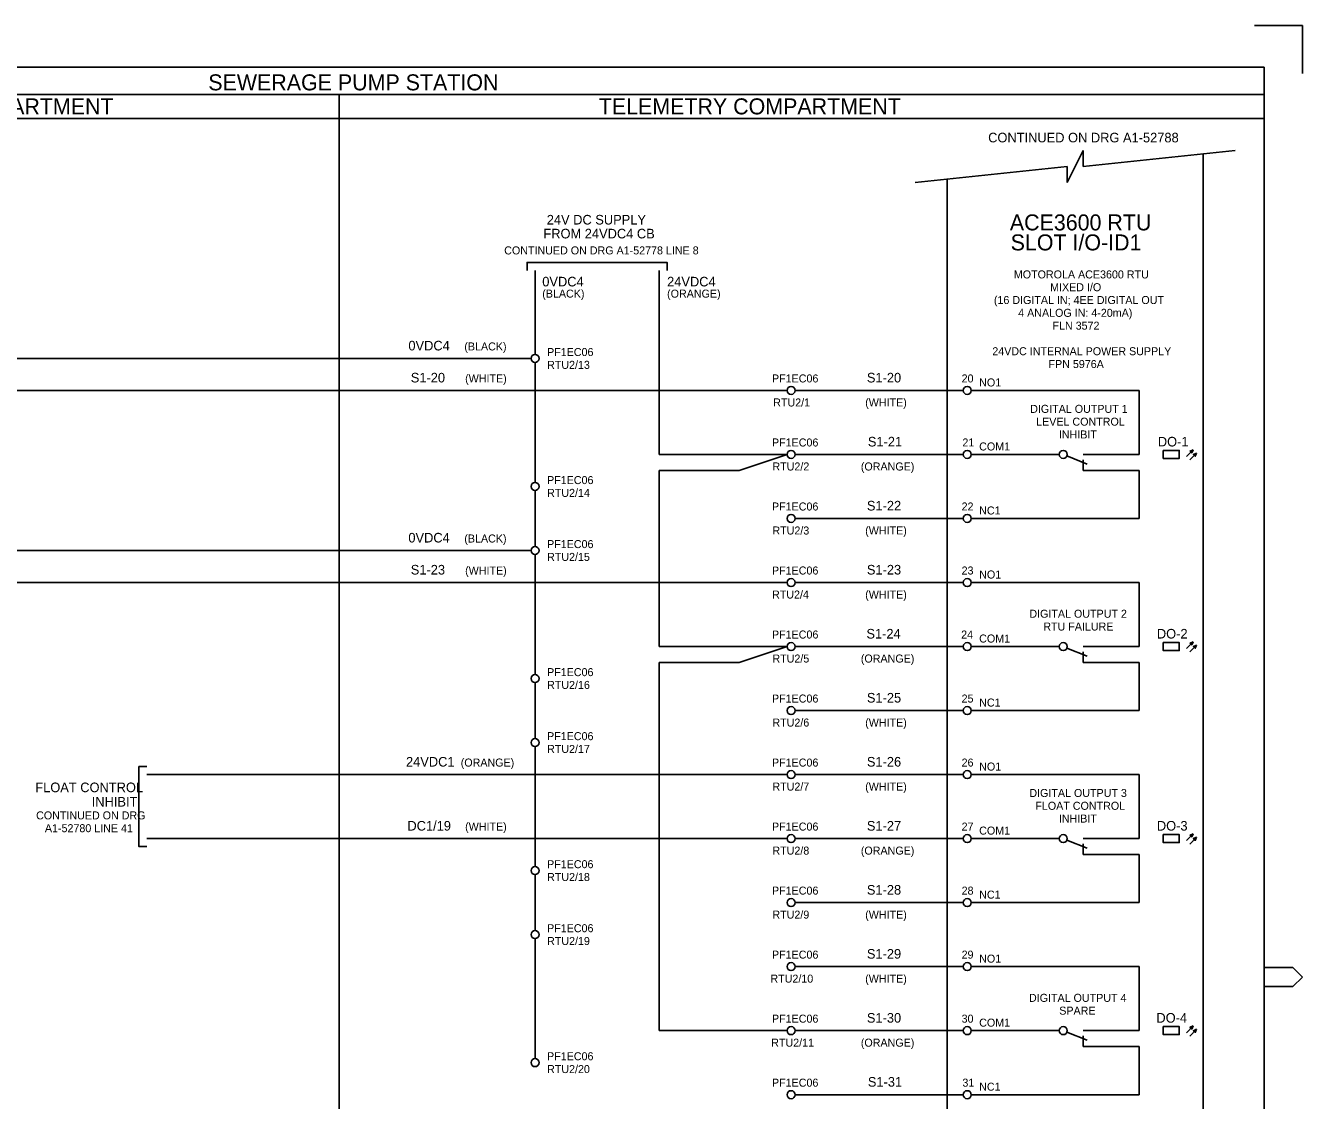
# Model space of a CAD drawing. Extents: x 0 to 841, y 0 to 594.
# Drawn here: x 442.1 to 841, y 258.2 to 594 of the extents above; entities that cross this region are included whole.
import ezdxf

# ---------------------------------------------------------------- set-up
doc = ezdxf.new("R2010")
doc.units = 0
for name, color, linetype in [('A1BORDER', 7, 'Continuous'), ('Level 1', 7, 'Continuous'), ('Level 10', 7, 'Continuous'), ('Level 2', 7, 'Continuous')]:
    doc.layers.add(name, color=color, linetype=linetype)

msp = doc.modelspace()

# ---------------------------------------------------------------- linework, layer by layer
at = {"layer": 'A1BORDER'}
for p, q in [((826, 594), (841, 594)), ((841, 579), (841, 594)), ((28, 581), (829, 581)), ((829, 581), (829, 15)), ((829, 299.76), (838, 299.76)), ((838, 299.76), (841, 296.76)), ((838, 293.76), (841, 296.76)), ((829, 293.76), (838, 293.76))]:
    msp.add_line(p, q, dxfattribs=at)
at = {"layer": 'Level 1'}
for p, q in [((829, 572.5), (160, 572.5)), ((540, 572.5), (540, 57)), ((829, 565), (160, 565)), ((772.5, 555), (767.5, 545)), ((772.5, 555), (772.5, 550)), ((772.5, 550), (820, 555)), ((767.5, 550), (720, 545)), ((767.5, 545), (767.5, 550)), ((601.25, 491.25), (601.25, 517.5)), ((640, 517.5), (640, 460)), ((382.5, 490), (600, 490)), ((601.25, 451.25), (601.25, 488.75)), ((680, 480), (350, 480)), ((735, 480), (682.5, 480)), ((790, 480), (737.5, 480)), ((790, 480), (790, 460)), ((680, 460), (640, 460)), ((680, 460), (665, 455)), ((735, 460), (682.5, 460)), ((765, 460), (737.5, 460)), ((790, 460), (775, 460)), ((665, 455), (640, 455)), ((640, 455), (640, 400)), ((790, 455), (775, 455)), ((790, 455), (790, 440)), ((601.25, 431.25), (601.25, 448.75)), ((735, 440), (682.5, 440)), ((790, 440), (737.5, 440)), ((382.5, 430), (600, 430)), ((601.25, 391.25), (601.25, 428.75)), ((680, 420), (350, 420)), ((735, 420), (682.5, 420)), ((790, 420), (737.5, 420)), ((790, 420), (790, 400)), ((680, 400), (640, 400)), ((680, 400), (665, 395)), ((735, 400), (682.5, 400)), ((765, 400), (737.5, 400)), ((790, 400), (775, 400)), ((640, 395), (640, 280)), ((665, 395), (640, 395)), ((790, 395), (775, 395)), ((790, 395), (790, 380)), ((601.25, 371.25), (601.25, 388.75)), ((735, 380), (682.5, 380)), ((790, 380), (737.5, 380)), ((601.25, 331.25), (601.25, 368.75)), ((680, 360), (480, 360)), ((735, 360), (682.5, 360)), ((790, 360), (737.5, 360)), ((790, 360), (790, 340)), ((680, 340), (480, 340)), ((735, 340), (682.5, 340)), ((765, 340), (737.5, 340)), ((790, 340), (775, 340)), ((790, 335), (775, 335)), ((790, 335), (790, 320)), ((601.25, 311.25), (601.25, 328.75)), ((735, 320), (682.5, 320)), ((790, 320), (737.5, 320)), ((601.25, 271.25), (601.25, 308.75)), ((735, 300), (682.5, 300)), ((790, 300), (737.5, 300)), ((790, 300), (790, 280)), ((680, 280), (640, 280)), ((735, 280), (682.5, 280)), ((765, 280), (737.5, 280)), ((790, 280), (775, 280)), ((790, 275), (775, 275)), ((790, 275), (790, 260)), ((735, 260), (682.5, 260)), ((790, 260), (737.5, 260))]:
    msp.add_line(p, q, dxfattribs=at)
for points in [[(810, 553.95), (810, 80), (730, 80), (730, 546.05)], [(598.75, 517.5), (598.75, 520), (642.5, 520), (642.5, 517.5)], [(480, 362.5), (477.5, 362.5), (477.5, 337.5), (480, 337.5)]]:
    msp.add_lwpolyline(points, dxfattribs=at)
for points in [[(797.5, 461.25), (802.5, 461.25), (802.5, 458.75), (797.5, 458.75)], [(797.5, 401.25), (802.5, 401.25), (802.5, 398.75), (797.5, 398.75)], [(797.5, 341.25), (802.5, 341.25), (802.5, 338.75), (797.5, 338.75)], [(797.5, 281.25), (802.5, 281.25), (802.5, 278.75), (797.5, 278.75)]]:
    msp.add_lwpolyline(points, close=True, dxfattribs=at)
at = {"layer": 'Level 10'}
for p, q in [((767.41, 459.54), (773.75, 457)), ((772.5, 460), (775, 460)), ((804.73, 459.36), (806.86, 461.48)), ((805.79, 458.3), (807.91, 460.42)), ((805.96, 461.07), (806.67, 461.07)), ((806, 460.93), (806.61, 460.93)), ((806.14, 460.78), (806.53, 460.78)), ((806.29, 461.23), (806.74, 461.23)), ((806.3, 460.62), (806.47, 460.62)), ((806.62, 461.38), (806.81, 461.38)), ((807.02, 460.01), (807.73, 460.01)), ((807.06, 459.87), (807.66, 459.87)), ((807.21, 459.72), (807.6, 459.72)), ((807.35, 460.17), (807.8, 460.17)), ((807.36, 459.56), (807.53, 459.56)), ((807.68, 460.31), (807.87, 460.31)), ((772.5, 458.37), (772.5, 455)), ((772.5, 455), (775, 455)), ((767.41, 399.54), (773.75, 397)), ((772.5, 400), (775, 400)), ((804.73, 399.36), (806.86, 401.48)), ((805.79, 398.3), (807.91, 400.42)), ((805.96, 401.07), (806.67, 401.07)), ((806, 400.93), (806.61, 400.93)), ((806.14, 400.78), (806.53, 400.78)), ((806.29, 401.23), (806.74, 401.23)), ((806.3, 400.62), (806.47, 400.62)), ((806.62, 401.38), (806.81, 401.38)), ((807.02, 400.01), (807.73, 400.01)), ((807.06, 399.87), (807.66, 399.87)), ((807.21, 399.72), (807.6, 399.72)), ((807.35, 400.17), (807.8, 400.17)), ((807.36, 399.56), (807.53, 399.56)), ((807.68, 400.31), (807.87, 400.31)), ((772.5, 398.37), (772.5, 395)), ((772.5, 395), (775, 395)), ((767.41, 339.54), (773.75, 337)), ((772.5, 340), (775, 340)), ((804.73, 339.36), (806.86, 341.48)), ((805.79, 338.3), (807.91, 340.42)), ((805.96, 341.07), (806.67, 341.07)), ((806, 340.93), (806.61, 340.93)), ((806.14, 340.78), (806.53, 340.78)), ((806.29, 341.23), (806.74, 341.23)), ((806.3, 340.62), (806.47, 340.62)), ((806.62, 341.38), (806.81, 341.38)), ((807.02, 340.01), (807.73, 340.01)), ((807.06, 339.87), (807.66, 339.87)), ((807.21, 339.72), (807.6, 339.72)), ((807.35, 340.17), (807.8, 340.17)), ((807.36, 339.56), (807.53, 339.56)), ((807.68, 340.31), (807.87, 340.31)), ((772.5, 338.37), (772.5, 335)), ((772.5, 335), (775, 335)), ((767.41, 279.54), (773.75, 277)), ((772.5, 280), (775, 280)), ((804.73, 279.36), (806.86, 281.48)), ((805.79, 278.3), (807.91, 280.42)), ((805.96, 281.07), (806.67, 281.07)), ((806, 280.93), (806.61, 280.93)), ((806.14, 280.78), (806.53, 280.78)), ((806.29, 281.23), (806.74, 281.23)), ((806.3, 280.62), (806.47, 280.62)), ((806.62, 281.38), (806.81, 281.38)), ((807.02, 280.01), (807.73, 280.01)), ((807.06, 279.87), (807.66, 279.87)), ((807.21, 279.72), (807.6, 279.72)), ((807.35, 280.17), (807.8, 280.17)), ((807.36, 279.56), (807.53, 279.56)), ((807.68, 280.31), (807.87, 280.31)), ((772.5, 278.37), (772.5, 275)), ((772.5, 275), (775, 275))]:
    msp.add_line(p, q, dxfattribs=at)
for points in [[(806.86, 461.48), (805.88, 461.04), (806.41, 460.5)], [(807.91, 460.42), (806.94, 459.98), (807.48, 459.44)], [(806.86, 401.48), (805.88, 401.04), (806.41, 400.5)], [(807.91, 400.42), (806.94, 399.98), (807.48, 399.44)], [(806.86, 341.48), (805.88, 341.04), (806.41, 340.5)], [(807.91, 340.42), (806.94, 339.98), (807.48, 339.44)], [(806.86, 281.48), (805.88, 281.04), (806.41, 280.5)], [(807.91, 280.42), (806.94, 279.98), (807.48, 279.44)]]:
    msp.add_lwpolyline(points, close=True, dxfattribs=at)
for centre in [(601.25, 490), (681.25, 480), (736.25, 480), (681.25, 460), (736.25, 460), (766.25, 460), (601.25, 450), (681.25, 440), (736.25, 440), (601.25, 430), (681.25, 420), (736.25, 420), (681.25, 400), (736.25, 400), (766.25, 400), (601.25, 390), (681.25, 380), (736.25, 380), (601.25, 370), (681.25, 360), (736.25, 360), (681.25, 340), (736.25, 340), (766.25, 340), (601.25, 330), (681.25, 320), (736.25, 320), (601.25, 310), (681.25, 300), (736.25, 300), (681.25, 280), (736.25, 280), (766.25, 280), (601.25, 270), (681.25, 260), (736.25, 260)]:
    msp.add_circle(centre, 1.25, dxfattribs=at)

# ---------------------------------------------------------------- texts
at = {"layer": 'Level 1'}
for s, height, p in [('SEWERAGE PUMP STATION', 5, (499.16, 573.75)), ('CONTROL COMPARTMENT', 5, (382.65, 566.25)), ('TELEMETRY COMPARTMENT', 5, (621.16, 566.25)), ('CONTINUED ON DRG A1-52788', 3, (742.81, 557.5)), ('24V DC SUPPLY', 3, (604.91, 531.84)), ('ACE3600 RTU', 5, (749.58, 530)), ('FROM 24VDC4 CB', 3, (603.86, 527.5)), ('SLOT I/O-ID1', 5, (749.83, 523.75)), ('CONTINUED ON DRG A1-52778 LINE 8', 2.5, (591.61, 522.5)), ('0VDC4', 3, (603.5, 512.5)), ('24VDC4', 3, (642.5, 512.5)), ('MOTOROLA ACE3600 RTU', 2.5, (750.83, 515)), ('(BLACK)', 2.5, (603.5, 509)), ('(ORANGE)', 2.5, (642.5, 509)), ('MIXED I/O', 2.5, (762.16, 511)), ('(16 DIGITAL IN; 4EE DIGITAL OUT', 2.5, (744.6, 507)), ('4 ANALOG IN: 4-20mA)', 2.5, (752.19, 503)), ('FLN 3572', 2.5, (762.9, 499)), ('0VDC4', 3, (561.68, 492.5)), ('(BLACK)', 2.5, (579.15, 492.5)), ('PF1EC06', 2.5, (605, 490.75)), ('24VDC INTERNAL POWER SUPPLY', 2.5, (744.1, 491)), ('RTU2/13', 2.5, (605, 486.75)), ('FPN 5976A', 2.5, (761.66, 487)), ('S1-20', 3, (562.42, 482.5)), ('(WHITE)', 2.5, (579.4, 482.5)), ('PF1EC06', 2.5, (675.27, 482.5)), ('S1-20', 3, (704.92, 482.5)), ('20', 2.5, (734.51, 482.5)), ('NO1', 2.5, (740, 481.25)), ('RTU2/1', 2.5, (675.65, 475)), ('(WHITE)', 2.5, (704.39, 475)), ('DIGITAL OUTPUT 1', 2.5, (755.93, 473)), ('LEVEL CONTROL', 2.5, (757.8, 469)), ('INHIBIT', 2.5, (764.9, 465)), ('PF1EC06', 2.5, (675.27, 462.5)), ('S1-21', 3, (705.22, 462.5)), ('21', 2.5, (734.76, 462.5)), ('COM1', 2.5, (740, 461.25)), ('DO-1', 3, (795.82, 462.5)), ('RTU2/2', 2.5, (675.4, 455)), ('(ORANGE)', 2.5, (703.03, 455)), ('PF1EC06', 2.5, (675.27, 442.5)), ('S1-22', 3, (704.92, 442.5)), ('22', 2.5, (734.51, 442.5)), ('NC1', 2.5, (740, 441.25)), ('0VDC4', 3, (561.67, 432.5)), ('(BLACK)', 2.5, (579.15, 432.5)), ('RTU2/3', 2.5, (675.4, 435)), ('(WHITE)', 2.5, (704.39, 435)), ('S1-23', 3, (562.42, 422.5)), ('(WHITE)', 2.5, (579.4, 422.5)), ('PF1EC06', 2.5, (675.27, 422.5)), ('S1-23', 3, (704.92, 422.5)), ('23', 2.5, (734.51, 422.5)), ('NO1', 2.5, (740, 421.25)), ('RTU2/4', 2.5, (675.28, 415)), ('(WHITE)', 2.5, (704.39, 415)), ('DIGITAL OUTPUT 2', 2.5, (755.68, 409)), ('RTU FAILURE', 2.5, (760.04, 405)), ('PF1EC06', 2.5, (675.27, 402.5)), ('S1-24', 3, (704.77, 402.5)), ('24', 2.5, (734.38, 402.5)), ('COM1', 2.5, (740, 401.25)), ('DO-2', 3, (795.52, 402.5)), ('RTU2/5', 2.5, (675.4, 395)), ('(ORANGE)', 2.5, (703.03, 395)), ('PF1EC06', 2.5, (675.27, 382.5)), ('S1-25', 3, (704.92, 382.5)), ('25', 2.5, (734.51, 382.5)), ('NC1', 2.5, (740, 381.25)), ('RTU2/6', 2.5, (675.4, 375)), ('(WHITE)', 2.5, (704.39, 375)), ('24VDC1', 3, (560.93, 362.5)), ('(ORANGE)', 2.5, (578.03, 362.5)), ('PF1EC06', 2.5, (675.27, 362.5)), ('S1-26', 3, (704.92, 362.5)), ('26', 2.5, (734.51, 362.5)), ('NO1', 2.5, (740, 361.25)), ('FLOAT CONTROL', 3, (445.12, 354.5)), ('RTU2/7', 2.5, (675.4, 355)), ('(WHITE)', 2.5, (704.39, 355)), ('DIGITAL OUTPUT 3', 2.5, (755.68, 353)), ('INHIBIT', 3, (462.75, 350)), ('FLOAT CONTROL', 2.5, (757.55, 349)), ('CONTINUED ON DRG', 2.5, (445.37, 346)), ('INHIBIT', 2.5, (764.9, 345)), ('A1-52780 LINE 41', 2.5, (448.11, 342)), ('DC1/19', 3, (561.37, 342.5)), ('(WHITE)', 2.5, (579.4, 342.5)), ('PF1EC06', 2.5, (675.27, 342.5)), ('S1-27', 3, (704.92, 342.5)), ('27', 2.5, (734.51, 342.5)), ('COM1', 2.5, (740, 341.25)), ('DO-3', 3, (795.52, 342.5)), ('RTU2/8', 2.5, (675.4, 335)), ('(ORANGE)', 2.5, (703.03, 335)), ('PF1EC06', 2.5, (675.27, 322.5)), ('S1-28', 3, (704.92, 322.5)), ('28', 2.5, (734.51, 322.5)), ('NC1', 2.5, (740, 321.25)), ('RTU2/9', 2.5, (675.4, 315)), ('(WHITE)', 2.5, (704.39, 315)), ('PF1EC06', 2.5, (675.27, 302.5)), ('S1-29', 3, (704.92, 302.5)), ('29', 2.5, (734.51, 302.5)), ('NO1', 2.5, (740, 301.25)), ('RTU2/10', 2.5, (674.78, 295)), ('(WHITE)', 2.5, (704.39, 295)), ('DIGITAL OUTPUT 4', 2.5, (755.56, 289)), ('SPARE', 2.5, (765.02, 285)), ('PF1EC06', 2.5, (675.27, 282.5)), ('S1-30', 3, (704.92, 282.5)), ('30', 2.5, (734.51, 282.5)), ('COM1', 2.5, (740, 281.25)), ('DO-4', 3, (795.37, 282.5)), ('RTU2/11', 2.5, (675.03, 275)), ('(ORANGE)', 2.5, (703.03, 275)), ('PF1EC06', 2.5, (675.27, 262.5)), ('S1-31', 3, (705.22, 262.5)), ('31', 2.5, (734.76, 262.5)), ('NC1', 2.5, (740, 261.25))]:
    msp.add_text(s, height=height, dxfattribs=at).set_placement(p)
at = {"layer": 'Level 2'}
for s, p in [('PF1EC06', (605, 450.75)), ('RTU2/14', (605, 446.75)), ('PF1EC06', (605, 430.75)), ('RTU2/15', (605, 426.75)), ('PF1EC06', (605, 390.75)), ('RTU2/16', (605, 386.75)), ('PF1EC06', (605, 370.75)), ('RTU2/17', (605, 366.75)), ('PF1EC06', (605, 330.75)), ('RTU2/18', (605, 326.75)), ('PF1EC06', (605, 310.75)), ('RTU2/19', (605, 306.75)), ('PF1EC06', (605, 270.75)), ('RTU2/20', (605, 266.75))]:
    msp.add_text(s, height=2.5, dxfattribs=at).set_placement(p)

doc.saveas('drawing.dxf')
